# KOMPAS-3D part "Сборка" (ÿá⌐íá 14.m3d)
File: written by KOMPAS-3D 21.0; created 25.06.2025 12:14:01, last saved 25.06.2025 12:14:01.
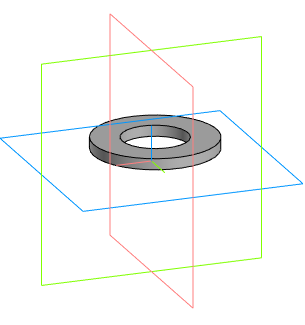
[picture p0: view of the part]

Document properties: Автор: PC321; Полное имя файла: C:\Users\PC321\Desktop\Шайба 14.m3d

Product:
- Part/product: Сборка
    Масса: 0.017195
  - Component [standard]: Шайба A.14.37 ГОСТ 11371-78  | pos. 1  | Материал: АД1 ГОСТ 4784-97 (density 1000 kg/m3); Масса: 0.008612; Раздел спецификации: Стандартные изделия; Рассекать на разрезах: no

Referenced files in C:\Program Files\ASCON\KOMPAS-3D v21 Study\Libs\PARTLib\DATA\vault\Methods\Kompas\3D\: PLib_Washer_1_712.m3d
